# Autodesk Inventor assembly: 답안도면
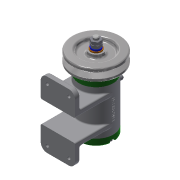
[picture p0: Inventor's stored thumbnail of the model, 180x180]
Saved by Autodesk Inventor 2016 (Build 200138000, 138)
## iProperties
Created: 2017-02
Part Number: 답안도면
Material: 일반
Document SubType Name: Assembly
Designer: CAMTIC
Author: CAMTIC
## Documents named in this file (16)
- C:\Users\CAMTIC\Desktop\470207V1017\답안조립품.iam
- C:\Users\CAMTIC\Desktop\470207V1017\본체.ipt
- C:\Users\CAMTIC\Desktop\470207V1017\470207V1017\축.ipt
- C:\Users\CAMTIC\Desktop\470207V1017\470207V1017\키 3 x 3 x 12.ipt
- C:\Users\CAMTIC\Desktop\470207V1017\470207V1017\베어링 15 x 32 x 9.ipt
- C:\Users\CAMTIC\Desktop\470207V1017\470207V1017\V벨트풀리.ipt
- C:\Users\CAMTIC\Desktop\470207V1017\470207V1017\너트 M 8.ipt
- C:\Users\CAMTIC\Desktop\470207V1017\470207V1017\니플 M 6 x 0.75.ipt
- C:\Users\CAMTIC\Desktop\470207V1017\470207V1017\뒤커버.ipt
- C:\Users\CAMTIC\Desktop\470207V1017\470207V1017\볼트 M 6 x 8.ipt
- C:\Users\CAMTIC\Desktop\470207V1017\470207V1017\볼트 M4 x 12.ipt
- C:\Users\CAMTIC\Desktop\470207V1017\470207V1017\스프링와셔 8.ipt
- C:\Users\CAMTIC\Desktop\470207V1017\470207V1017\앞커버.ipt
- C:\Users\CAMTIC\Desktop\470207V1017\470207V1017\오일 실 15 25 7.ipt
- C:\Users\CAMTIC\Desktop\470207V1017\470207V1017\와셔 6x11.5.ipt
- C:\Users\CAMTIC\Desktop\470207V1017\470207V1017\와셔 8x17.ipt
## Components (11 placed, 3 different names)
1. KS B 2023 6002 - 15 x 32 x 9:1
2. KS B 2023 6002 - 15 x 32 x 9:2
3. V벨트풀리:1
4. ISO 4762 M4 x 12:2
5. ISO 4762 M4 x 12:3
6. ISO 4762 M4 x 12:4
7. ISO 4762 M4 x 12:5
8. ISO 4762 M4 x 12:1
9. ISO 4762 M4 x 12:6
10. ISO 4762 M4 x 12:7
11. ISO 4762 M4 x 12:8
